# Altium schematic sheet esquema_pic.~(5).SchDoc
size A4
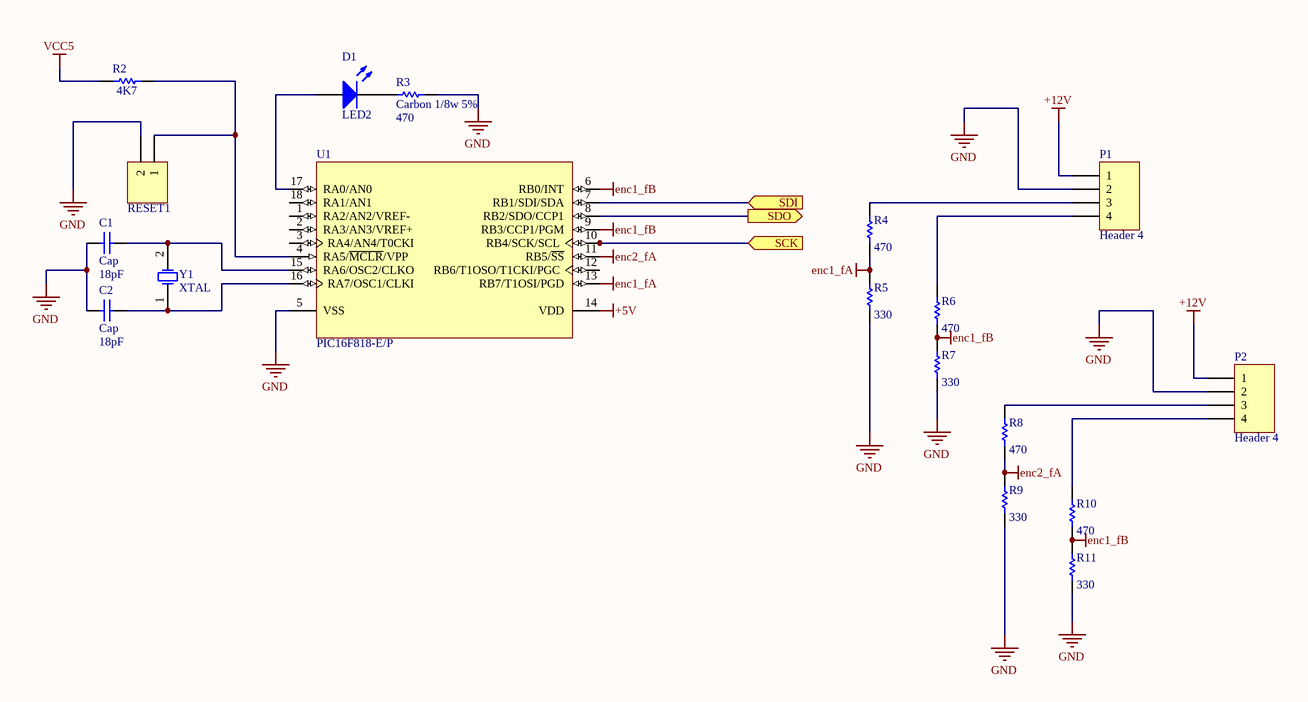
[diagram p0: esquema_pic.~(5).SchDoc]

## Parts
C1  Cap  value 18pF  [RAD-0.3]
C2  Cap  value 18pF  [RAD-0.3]
D1  LED2  [3.2X1.6X1.1]
P1  Header 4  [HDR1X4]
P2  Header 4  [HDR1X4]
R2  value 4K7  [1005[0402]]  (hidden comment: Carbon 1/8w 5%)
R3  Carbon 1/8w 5%  value 470  [1005[0402]]
R4  value 470  [1005[0402]]  (hidden comment: metal film 2%)
R5  value 330  [1005[0402]]  (hidden comment: metal film 2%)
R6  value 470  [1005[0402]]  (hidden comment: metal film 2%)
R7  value 330  [1005[0402]]  (hidden comment: metal film 2%)
R8  value 470  [1005[0402]]  (hidden comment: metal film 2%)
R9  value 330  [1005[0402]]  (hidden comment: metal film 2%)
R10  value 470  [1005[0402]]  (hidden comment: metal film 2%)
R11  value 330  [1005[0402]]  (hidden comment: metal film 2%)
RESET1  Header 2  [HDR1X2]  (value not drawn)
U1  PIC16F818-E/P  [PDIP300-18]
Y1  XTAL  [R38]

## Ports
SCK (in), SDI (in), SDO (out)

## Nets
+5V: U1.14(VDD)
+12V: P1.1 P2.1
enc1_fA: R4.1 R5.2 U1.13(RB7/T1OSI/PGD)
enc1_fB: R6.1 R7.2 R10.1 R11.2 U1.6(RB0/INT) U1.9(RB3/CCP1/PGM)
enc2_fA: R8.1 R9.2 U1.11(RB5/~{SS})
GND: C1.1 C2.1 P1.2 P2.2 R3.2 R5.1 R7.1 R9.1 R11.1 RESET1.2 U1.5(VSS)
VCC5: R2.1
SCK: U1.10(RB4/SCK/SCL) ; port SCK
SDI: U1.7(RB1/SDI/SDA) ; port SDI
SDO: U1.8(RB2/SDO/CCP1) ; port SDO
NetC1_2: C1.2 U1.15(RA6/OSC2/CLKO) Y1.2(OSC2)
NetC2_2: C2.2 U1.16(RA7/OSC1/CLKI) Y1.1(OSC1)
NetD1_1: D1.1(A) U1.17(RA0/AN0)
NetD1_2: D1.2(K) R3.1
NetP1_3: P1.3 R4.2
NetP1_4: P1.4 R6.2
NetP2_3: P2.3 R8.2
NetP2_4: P2.4 R10.2
NetR2_2: R2.2 RESET1.1 U1.4(RA5/~{MCLR}/VPP)

Not connected (* = marked no-connect by the designer): U1 1(RA2/AN2/VREF-) 2(RA3/AN3/VREF+) 3(RA4/AN4/T0CKI) 12(RB6/T1OSO/T1CKI/PGC) 18(RA1/AN1)

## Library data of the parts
C1 C2 = Cap: Capacitor
D1 = LED2: Typical RED, GREEN, YELLOW, AMBER GaAs LED
P1 P2 = Header 4: Header, 4-Pin
R2-R11 = Res Semi: Semiconductor Resistor
RESET1 = Header 2: Header, 2-Pin
U1 = PIC16F818-E/P: Enhanced FLASH Microcontroller with nanoWatt Technology, 1K (x14-Bit words) FLASH, 128 Bytes RAM, 18-Pin PDIP, Standard VDD Range, Extended Temperature
Y1 = XTAL: Crystal Oscillator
